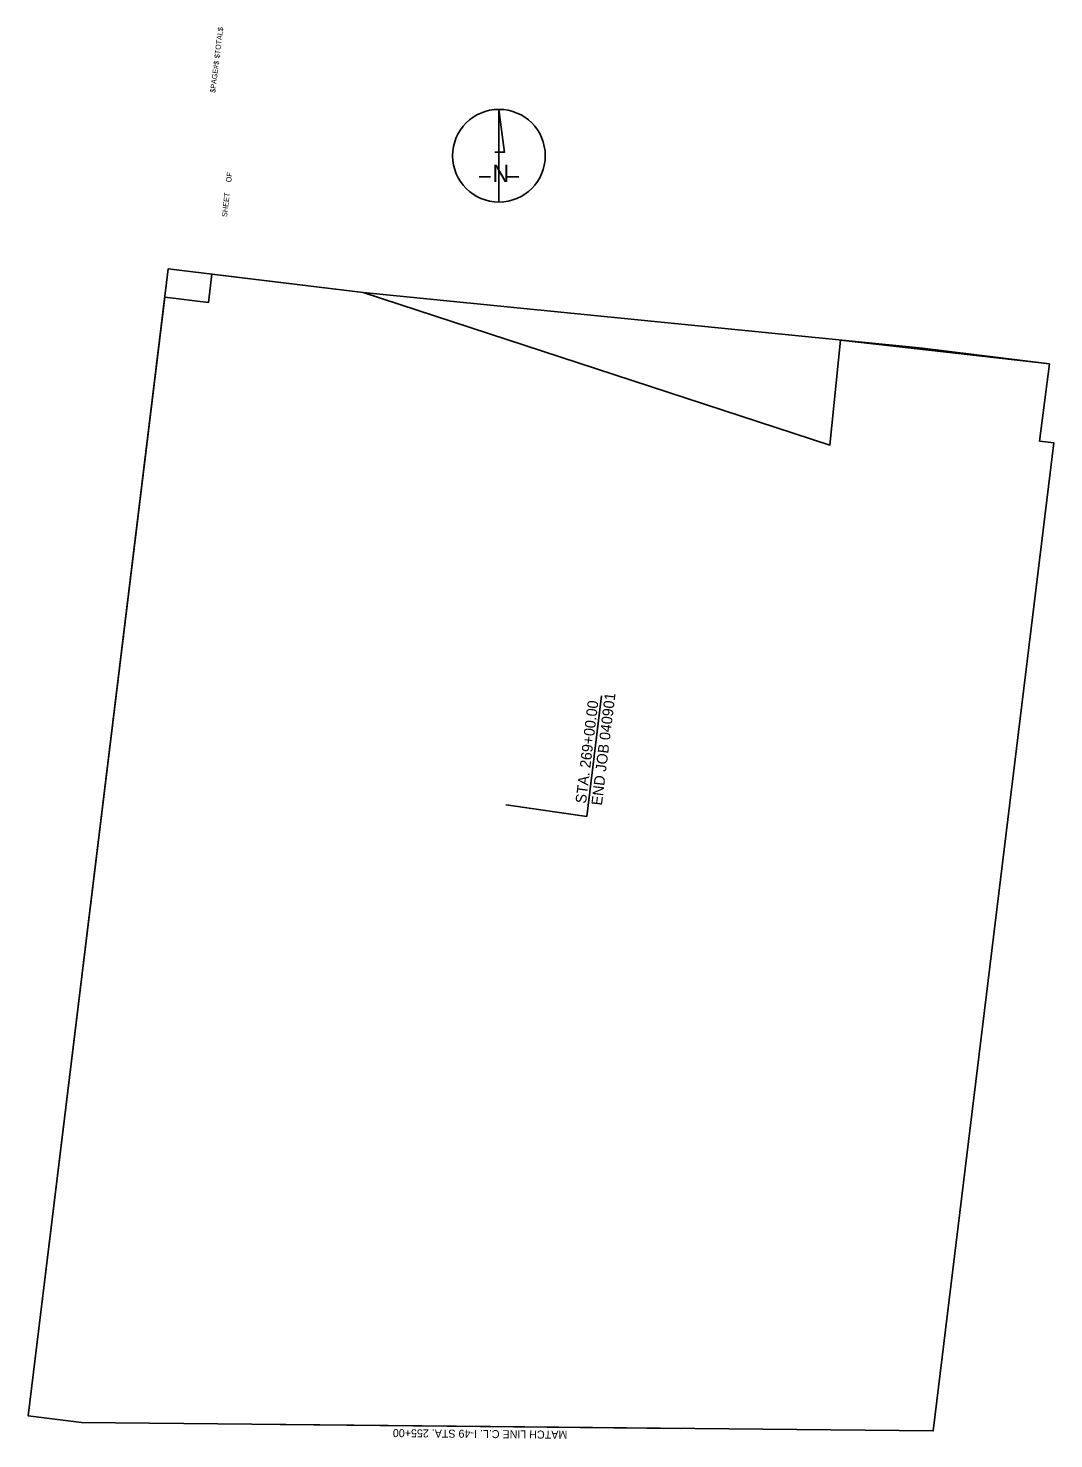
# Model space of a CAD drawing. Extents: x 631349 to 633656, y 382304 to 385478.
import ezdxf

# ---------------------------------------------------------------- set-up
doc = ezdxf.new("R2010")
doc.units = 0
for name, color, linetype in [('Copy of R_Dimension', 7, 'Continuous'), ('R_Border_N Arrow', 7, 'Continuous'), ('R_Draft', 7, 'Continuous'), ('S_DITCHLINE', 7, 'Continuous'), ('S_ELECTRIC_UTILITIES', 7, 'Continuous')]:
    doc.layers.add(name, color=color, linetype=linetype)

msp = doc.modelspace()

# ---------------------------------------------------------------- linework, layer by layer
at = {"layer": 'Copy of R_Dimension'}
msp.add_line((632408.1, 385295), (632408.1, 385086.7), dxfattribs=at)
msp.add_lwpolyline([(633656.5, 384544.9), (633624.7, 384548.6), (633646.5, 384722.5), (633361.3, 384757.7), (632102.5, 384883), (632102.5, 384883), (631664.2, 384936.5), (631348.9, 382355.7), (631468.5, 382341.1), (633385.1, 382322.1)], close=True, dxfattribs=at)
msp.add_lwpolyline([(631348.9, 382355.7), (631656.4, 384872.4), (631754.4, 384860.4), (631762.3, 384924.5), (632102.5, 384883), (633152.9, 384539.7), (633176.5, 384776.1), (633646.5, 384722.5), (633624.7, 384548.6), (633656.5, 384544.9), (633385.1, 382322.1), (631468.5, 382341.1), (631348.9, 382355.7)], dxfattribs=at)
msp.add_circle((632408.1, 385190.8), 104.2, dxfattribs=at)
at = {"layer": 'R_Border_N Arrow'}
for p, q in [((632408.1, 385295), (632420.3, 385198)), ((632408.1, 385159.4), (632408.1, 385295)), ((632398.7, 385198.7), (632420.3, 385198.7)), ((632363.5, 385143.4), (632389.3, 385143.4)), ((632408.1, 385086.7), (632408.1, 385126.5)), ((632425.3, 385143.4), (632452.7, 385143.4))]:
    msp.add_line(p, q, dxfattribs=at)
at = {"layer": 'R_Draft'}
msp.add_line((631915.6, 382336.7), (632815.6, 382327.7), dxfattribs=at)
at = {"layer": 'S_ELECTRIC_UTILITIES'}
for p, q in [((632606, 383704.3), (632639.1, 383975.5)), ((632423.5, 383730.3), (632429.4, 383729.5)), ((632423.5, 383730.3), (632429.4, 383729.5)), ((632429.4, 383729.5), (632606, 383704.3))]:
    msp.add_line(p, q, dxfattribs=at)

# ---------------------------------------------------------------- texts
at = {"layer": 'Copy of R_Dimension'}
for s, p in [('OF', (631805.5, 385130.2)), ('SHEET', (631796, 385052.2))]:
    msp.add_text(s, height=12, rotation=83.0348, dxfattribs=at).set_placement(p)
at = {"layer": 'R_Border_N Arrow'}
msp.add_text('N', height=38.8, rotation=360, dxfattribs=at).set_placement((632393.4, 385131.5))
at = {"layer": 'R_Draft'}
for s, p in [('$TOTAL$', (631779.2, 385409.5)), ('$PAGE#$', (631769.7, 385331.9))]:
    msp.add_text(s, height=11.72, rotation=83.0348, dxfattribs=at).set_placement(p)
at = {"layer": 'S_DITCHLINE'}
msp.add_text('MATCH LINE C.L. I-49 STA. 255+00', height=18, rotation=179.4304, dxfattribs=at).set_placement((632562, 382322.2))
at = {"layer": 'S_ELECTRIC_UTILITIES'}
for s, p in [('END JOB 040901', (632639.6, 383728.1)), ('STA. 269+00.00', (632603.8, 383732.5))]:
    msp.add_text(s, height=24, rotation=83.0348, dxfattribs=at).set_placement(p)

doc.saveas('drawing.dxf')
